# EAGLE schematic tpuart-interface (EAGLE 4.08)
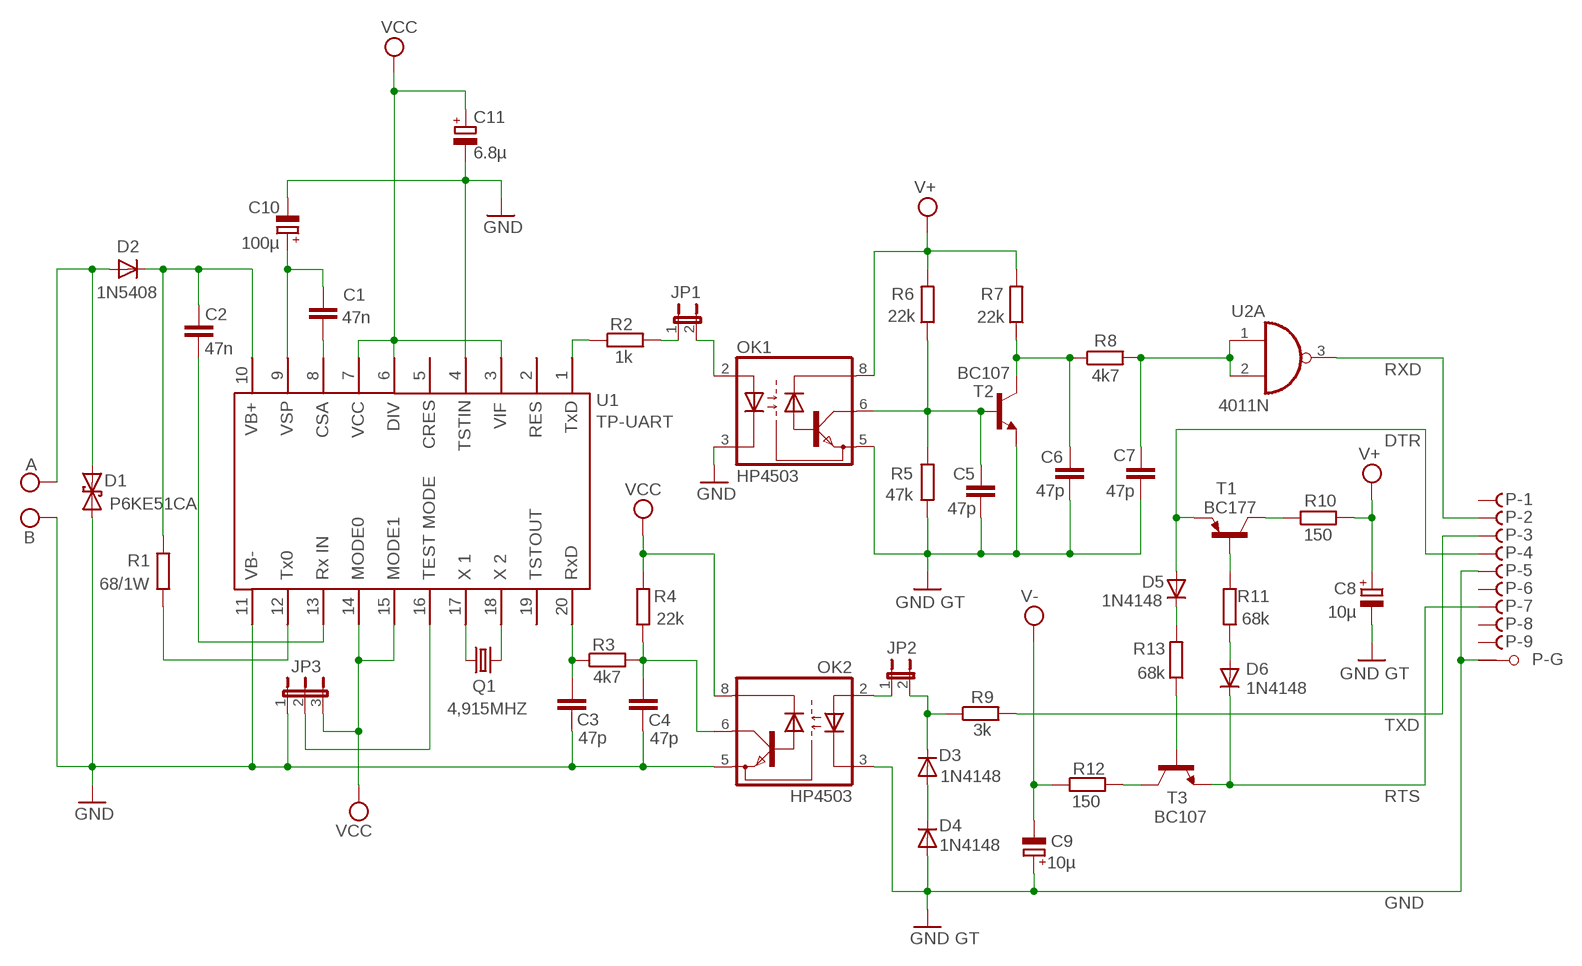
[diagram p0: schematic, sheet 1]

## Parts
A  W237-112  [W237-112]
B  W237-112  [W237-112]
C1  47n  C-EU025-025X050  [C025-025X050]
C2  47n  C-EU025-025X050  [C025-025X050]
C3  47p  C-EU025-025X050  [C025-025X050]
C4  47p  C-EU025-025X050  [C025-025X050]
C5  47p  C-EU025-025X050  [C025-025X050]
C6  47p  C-EU025-025X050  [C025-025X050]
C7  47p  C-EU025-025X050  [C025-025X050]
C8  10µ  CPOL-EUE5-4  [E5-4]
C9  10µ  CPOL-EUE5-4  [E5-4]
C10  100µ  CPOL-EUE5-4  [E5-4]
C11  6.8µ  CPOL-EUE5-4  [E5-4]
D1  P6KE51CA  15KEXXC  [CB429-17]
D2  1N5408  1N4148  [DO35-10]
D3  1N4148  [DO35-10]
D4  1N4148  [DO35-10]
D5  1N4148  [DO35-10]
D6  1N4148  [DO35-10]
JP1  JP1E  [JP1]
JP2  JP1E  [JP1]
JP3  JP2E  [JP2]
OK1  HP4503  HCPL0453  [SOIC08]
OK2  HP4503  HCPL0453  [SOIC08]
P  F09HPS  [F09HP]
Q1  4,915MHZ  HC18U-V  [HC18U-V]
R1  68/1W  R-EU_0207/10  [0207/10]
R2  1k  R-EU_0207/10  [0207/10]
R3  4k7  R-EU_0207/10  [0207/10]
R4  22k  R-EU_0207/10  [0207/10]
R5  47k  R-EU_0207/10  [0207/10]
R6  22k  R-EU_0207/10  [0207/10]
R7  22k  R-EU_0207/10  [0207/10]
R8  4k7  R-EU_0207/10  [0207/10]
R9  3k  R-EU_0207/10  [0207/10]
R10  150  R-EU_0207/10  [0207/10]
R11  68k  R-EU_0207/10  [0207/10]
R12  150  R-EU_0207/10  [0207/10]
R13  68k  R-EU_0207/10  [0207/10]
T1  BC177  [TO18]
T2  BC107  [TO18]
T3  BC107  [TO18]
U2  4011N  [DIL14]
U$1  TP-UART-ICBOARD  [TP-UART-BOARD]

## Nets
DTR: D5.A P.4(-4:F) T1.1(E)
GND: B.1(KL) C3.2 C4.2 C5.2 C6.2 C7.2 C8.- C9.+ D1.A D4.A JP3.1 OK1.3(C) OK2.5(GND) P.5(-5:F) P.G1(-G:G1) R5.1 T2.1(E) ; supply symbol labelled GND GT
N$1: C6.1 R7.1 R8.1 T2.3(C)
N$2: C7.1 R8.2 U2.1(A:I0) U2.2(A:I1)
N$4: JP1.2 OK1.2(A)
N$5: R5.2 R6.1 T2.2(B)
N$6: D3.A D4.C
N$7: Q1.2
N$8: Q1.1
N$9: C2.2
N$10: C5.1
N$11: R12.2 T3.3(C)
N$12: R13.1 T3.2(B)
N$13: D5.C R13.2
N$14: A.1(KL) D1.C D2.A
N$15: D3.C JP2.2 R9.1
N$16: R11.2 T1.2(B)
N$17: D6.A R11.1
N$18: C1.1 C10.+
N$19: R10.1 T1.3(C)
N$20: C3.1 R3.1
N$21: C10.- C11.- ; supply symbol labelled GND
N$22: R2.1
N$23: C2.1 D2.C R1.2
N$24: JP2.1
N$25: JP1.1 R2.2
N$26: R1.1
N$27: JP3.2
N$28: C4.1 OK2.6(VO) R3.2 R4.1
RTS: D6.C P.7(-7:F) T3.1(E)
RXD: P.2(-2:F) U2.3(A:O)
TP: C1.2
TXD: P.3(-3:F) R9.2
VCC: C8.+ C9.- C11.+ JP3.3 OK1.8(VCC) OK2.8(VCC) R4.2 R6.2 R7.2 R10.2 R12.1 ; supply symbol labelled V-, V+
Unconnected: OK1.5(GND) OK1.6(VO) OK2.2(A) OK2.3(C) P.1(-1:F) P.6(-6:F) P.8(-8:F) P.9(-9:F) P.G2(-G:G2) U2.4(B:O) U2.5(B:I0) U2.6(B:I1) U2.8(C:I0) U2.9(C:I1) U2.10(C:O) U2.11(D:O) U2.12(D:I0) U2.13(D:I1)

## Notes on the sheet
- U1
- TP-UART

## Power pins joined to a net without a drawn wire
VDD: U2.14(P:VDD)
VSS: U2.7(P:VSS)

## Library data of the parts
A B = con-wago-500:W237-112: WAGO SCREW CLAMP
C1-C7 = rcl:C-EU: CAPACITOR, European symbol
C8-C11 = rcl:CPOL-EU: POLARIZED CAPACITOR, European symbol
D1 = diode:15KEXXC: DIODE
D2-D6 = diode:1N4148: DIODE
JP1 JP2 = jumper:JP1E: JUMPER
JP3 = jumper:JP2E: JUMPER
OK1 OK2 = optocoupler:HCPL0453: HEWLETT PACKARD OPTO COUPLER
P = con-subd:F09HPS: SUB-D
Q1 = crystal:HC18U-V: CRYSTAL
R1-R13 = rcl:R-EU_: RESISTOR, European symbol
T1 = transistor-pnp:BC177: PNP TRANSISTOR
T2 T3 = transistor-npn:BC107: NPN TRANSISTOR
U2 = 40xx:4011: Quad 2-input NAND
U$1 = TPUART:TP-UART-IC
